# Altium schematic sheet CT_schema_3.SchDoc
size 307 x 173 mm
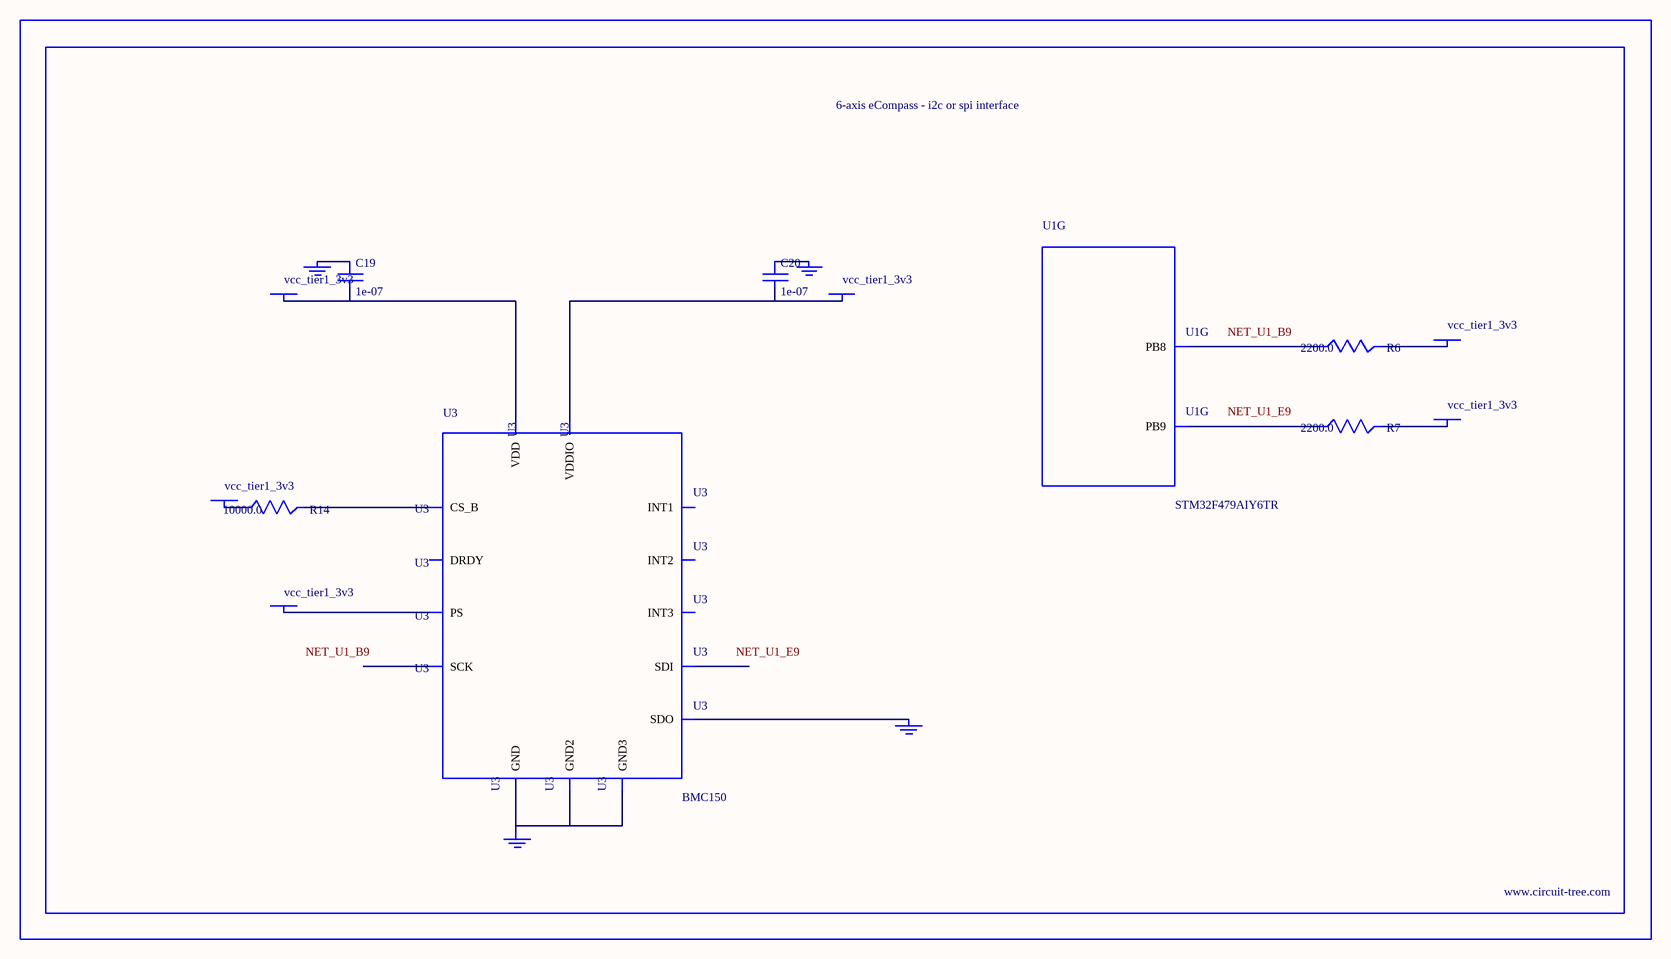
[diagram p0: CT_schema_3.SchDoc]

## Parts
BORDER2  (no value)
C19  1e-07  [C0402]
C20  1e-07  [C0402]
GND_INSTANCE_2_0  (no value)
GND_INSTANCE_2_1  (no value)
GND_INSTANCE_2_2  (no value)
GND_INSTANCE_2_3  (no value)
POWER_INSTANCE_2_0  vcc_tier1_3v3
POWER_INSTANCE_2_1  vcc_tier1_3v3
POWER_INSTANCE_2_2  vcc_tier1_3v3
POWER_INSTANCE_2_3  vcc_tier1_3v3
POWER_INSTANCE_2_4  vcc_tier1_3v3
POWER_INSTANCE_2_5  vcc_tier1_3v3
R6  2200.0  [R0603]
R7  2200.0  [R0603]
R14  10000.0  [R0603]
U1  STM32F479AIY6TR  [WLCSP168]  (part G of 13)
U3  BMC150  [LGA14R35P5X6_200X200X100]

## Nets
NetC19_1: C19.1 GND_INSTANCE_2_1.0(GND)
NetC19_2: C19.2 POWER_INSTANCE_2_0.0(PWR) U3.8(VDD)
NetC20_1: C20.1 GND_INSTANCE_2_2.0(GND)
NetC20_2: C20.2 POWER_INSTANCE_2_1.0(PWR) U3.10(VDDIO)
NetGND_INSTANCE_2_0_0: GND_INSTANCE_2_0.0(GND) U3.1(SDO)
NetGND_INSTANCE_2_3_0: GND_INSTANCE_2_3.0(GND) U3.6(GND) U3.7(GND2) U3.9(GND3)
NetPOWER_INSTANCE_2_2_0: POWER_INSTANCE_2_2.0(PWR) R14.1
NetPOWER_INSTANCE_2_3_0: POWER_INSTANCE_2_3.0(PWR) U3.13(PS)
NetPOWER_INSTANCE_2_4_0: POWER_INSTANCE_2_4.0(PWR) R6.2
NetPOWER_INSTANCE_2_5_0: POWER_INSTANCE_2_5.0(PWR) R7.2
NetR6_1: R6.1 U1.B9(PB8)
NetR7_1: R7.1 U1.E9(PB9)
NetR14_2: R14.2 U3.12(CS_B)

Not connected (* = marked no-connect by the designer): U3 2(INT1) 3(INT2) 4(DRDY) 5(INT3) 11(SCK) 14(SDI)

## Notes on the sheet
- Labels drawn without touching a wire or pin: NET_U1_B9, NET_U1_E9

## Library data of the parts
BORDER2 = BORDER_PAGE2
C19 C20 = C0402C104K3RACTU
GND_INSTANCE_2_0-GND_INSTANCE_2_3 = GND
POWER_INSTANCE_2_0-POWER_INSTANCE_2_5 = PWR
R6 R7 = RC0603JR-072K2L
R14 = RC0603JR-0710KL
